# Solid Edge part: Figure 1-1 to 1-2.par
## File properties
Author: CADCIM
Template: normal.par
Last saved by: CADCIM
Revision: 16
Application: Solid Edge
Accuracy: 0.99
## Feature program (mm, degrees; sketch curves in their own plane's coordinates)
sketch for "unnamed Protrusion 1" plane through (0, 0, 0) normal (0, 0, 1) x-axis (1, 0, 0)
  line (-63.0032, 49) -> (-56, -71)
  line (-56, -71) -> (56, -71)
  line (56, -71) -> (63.0032, 49)
  line (63.0032, 49) -> (0, 54)
  line (0, 54) -> (-63.0032, 49)
  dimension (linear) = 56
  dimension (linear) = 56
extrude "unnamed Protrusion 1" add finite 4 along +normal
fillet "Round_1" radius 15
sketch for "ExtrudedProtrusion_3" plane through (0, -8.5, 0) normal (0, 0, -1) x-axis (-1, 0, 0)
extrude "ExtrudedProtrusion_3" add finite 12 along -normal
pattern "unnamed Pattern 1" of "ExtrudedProtrusion_3"
pattern "unnamed Pattern 2"
sketch for "unnamed Protrusion 2" plane through (-1.0316, 2.3101, 4) normal (0, 0, 1) x-axis (-1, 0, 0)
extrude "unnamed Protrusion 2" add finite 5 along +normal
sketch for "Hole_22" plane through (40.9331, -54.9887, 12) normal (0, 0, 1) x-axis (1, 0, 0)
  hole centre (-0.4331, -0.0113) bore radius 4.5
hole "Hole_22" diameter 9 through  CounterBoreDepth = 5 mm
pattern "unnamed Pattern 3" of "Hole_22"
hole "unnamed Hole 1" through
hole "unnamed Hole 2" through
hole "unnamed Hole 3" through
sketch for "Hole_29" plane through (-1.0316, -6.1899, 9) normal (0, 0, 1) x-axis (1, 0, 0)
  hole centre (0, 0) bore radius 11
hole "Hole_29" diameter 22 through
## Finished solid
Body 1: solid body, 34 faces, 55 edges, 18 vertices.
  Faces by surface: cylinder 18, plane 16
  Edges by curve: circle 36, line 19
Bounding box of the edges (mm): 124.346 x 125.000 x 12.000, from (-62.1729, -71, 0) to (62.1729, 54, 12).
Cylindrical faces by radius (mm): R4.5 x4, R7.5 x4, R10.7006 x4, R11 x1, R15 x4, R20 x1
Planar faces by outward normal: +z 10, -y 1, -z 1, oblique 4
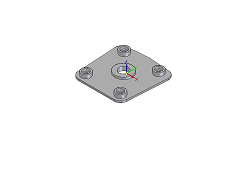
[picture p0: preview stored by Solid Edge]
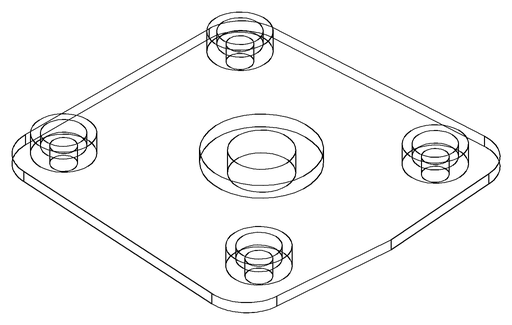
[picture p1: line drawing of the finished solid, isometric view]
